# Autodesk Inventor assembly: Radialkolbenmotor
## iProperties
Created: 2008-07
Part Number: Radialkolbenmotor
Document SubType Name: Assembly
Designer: WH
Übersetzungsnorm: STEP AP214IS
Dateiname: C:\Programme\Autodesk\Inventor 2009\Samples\Models\Radialkolbenmotor\Radialkolbenmotor.stp
Vorprozessor: Autodesk Inventor 2009
Postprozessor: Build: 236a, Release: 2009 RTM - Date: Fri 02/22/2008
Gesendete Einheiten: MM
Unbestimmtheit: 0.01
Author: WH
